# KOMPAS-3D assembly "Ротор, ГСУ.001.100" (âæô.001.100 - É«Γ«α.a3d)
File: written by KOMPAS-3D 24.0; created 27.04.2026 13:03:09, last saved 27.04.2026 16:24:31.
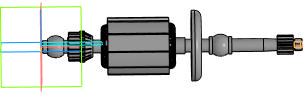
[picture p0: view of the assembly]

Document properties: Автор: User7; Полное имя файла: C:\Users\User7\Desktop\ГМ_27_04_337-02\ГСУ.001.100 - Ротор.a3d

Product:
- Component [detail]: Вал ротора  | designation ГСУ.001.102  | qty 1  | pos. 1  | Масса: 0.060205; Автор: User7; source file: ГСУ.001.102 - Вал ротора.m3d
- Component [detail]: Пропеллер  | designation ГСУ.001.104  | qty 1  | pos. 2  | Масса: 0.031447; Автор: User7; source file: ГСУ.001.104 - Пропеллер.m3d
- Component [detail]: Коллектор  | designation ГСУ.001.105  | qty 1  | pos. 3  | Масса: 0.0199; Автор: User7; source file: ГСУ.001.105 - Коллектор.m3d
- Component [detail]: Шайба  | designation ГСУ.001.106  | qty 2  | pos. 4  | Масса: 0.000703; Автор: User7; source file: ГСУ.001.106 - Шайба.m3d
- Component [detail]: Втулка  | designation ГСУ.001.107  | qty 2  | pos. 5  | Масса: 0.00612; Автор: User7; source file: ГСУ.001.107 - Втулка.m3d
- Component [detail]: Пластина  | designation ГСУ.001.108  | qty 10  | pos. 6  | Масса: 0.000055; Автор: User7; source file: ГСУ.001.108 - Пластина.m3d
- Component [detail]: Обмотка  | designation ГСУ.001.109  | qty 20  | pos. 7  | Масса: 0.002122; Автор: User7; source file: ГСУ.001.109 - Обмотка.m3d
- Component [detail]: Звездочка  | designation ГСУ.001.101  | qty 1  | pos. 8  | Масса: 0.070568; Автор: User7; source file: ГСУ.001.101 - Звездочка.m3d
- Component [standard]: Гайка М4-6H ГОСТ 15523-70  | qty 1  | Масса: 0.001183; Раздел спецификации: Стандартные изделия; Рассекать на разрезах: no
- Component [detail]: Шестеренка  | designation ГСУ.001.103  | qty 1  | pos. 9  | Масса: 0.003838; Автор: User7; source file: ГСУ.001.103 - Шестерня.m3d
- Component [detail]: Пластина  | designation ГСУ.001.110  | qty 10  | pos. 10  | Масса: 0.003574; Автор: User7; source file: ГСУ.001.110 - Пластина.m3d
- Part/product: Ротор  | designation ГСУ.001.100
    Масса: 0.279522

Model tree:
1. Средняя плоскость:1  (with: Грань.Элемент выдавливания:2)  (labels: Грань.Элемент выдавливания:2.Экземпляр ( 1, 2 ))
2. Массив по концентрической сетке:1  (with: Грань.Элемент вращения:1, Грань.Элемент выдавливания:1, Грань.Элемент выдавливания:2, Грань.Элемент по траектории:1, Средняя плоскость:1)  (labels: Грань.Элемент выдавливания:1.Экземпляр ( 110, 1 ); Грань.Элемент выдавливания:2.Экземпляр ( 1, 2 ))  (10 pattern instances)
     Шаг 2 = 360; Расстояние = -4; Расстояние = 2.5; Расстояние = 10; Расстояние = 19; Расстояние = 38.2; Расстояние = -162; Расстояние = 5.5; Расстояние = 19; Ориентация = 2; Угол = 162

Referenced files in C:\Users\User7\Desktop\ГМ_27_04_337-02\: ГСУ.001.102 - Вал ротора.m3d, ГСУ.001.104 - Пропеллер.m3d, ГСУ.001.105 - Коллектор.m3d, ГСУ.001.106 - Шайба.m3d, ГСУ.001.107 - Втулка.m3d, ГСУ.001.108 - Пластина.m3d, ГСУ.001.109 - Обмотка.m3d, ГСУ.001.101 - Звездочка.m3d, ГСУ.001.103 - Шестерня.m3d, ГСУ.001.110 - Пластина.m3d
Referenced files in C:\Program Files\ASCON\KOMPAS-3D v21\Libs\PARTLib\DATA\vault\Methods\Kompas\3D\: PLib_Nut_OST92_900.m3d
Referenced files in C:\Users\User7\Desktop\олимп\: ГСУ.001.106 - Шайба.m3d, ГСУ.001.107 - Втулка.m3d, ГСУ.001.108 - Пластина.m3d, ГСУ.001.110 - Пластина.m3d, ГСУ.001.109 - Обмотка.m3d
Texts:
  ГСУ.001.102
  ГСУ.001.104
  ГСУ.001.105
  ГСУ.001.106
  ГСУ.001.107
  ГСУ.001.108
  ГСУ.001.109
  ГСУ.001.101
  Крепежное изделие ГОСТ
  Программные изделия  и базы данных
  ГСУ.001.103
  ГСУ.001.110
  ГСУ.001.100
  Точка начала. Х
  Точка начала. Y
  Точка начала. Z
  ГСУ.001.102 Вал ротора
  ГСУ.001.104 Пропеллер
  ГСУ.001.105 Коллектор
  ГСУ.001.106 Шайба (1)
  ГСУ.001.107 Втулка (1)
  ГСУ.001.108 Пластина (1)
  ГСУ.001.109 Обмотка (1)
  ГСУ.001.101 Звездочка
  ГСУ.001.106 Шайба (2)
  ГСУ.001.107 Втулка (2)
  bcut1
  hole1
  hcut1
  hole2
  cut1
  ГСУ.001.103 Шестеренка
  ГСУ.001.110 Пластина (1)
  ГСУ.001.108 Пластина (2)
  ГСУ.001.110 Пластина (2)
  ГСУ.001.109 Обмотка (2)
  ГСУ.001.108 Пластина (3)
  ГСУ.001.110 Пластина (3)
  ГСУ.001.109 Обмотка (3)
  ГСУ.001.108 Пластина (4)
  ГСУ.001.110 Пластина (4)
  ГСУ.001.109 Обмотка (4)
  ГСУ.001.108 Пластина (5)
  ГСУ.001.110 Пластина (5)
  ГСУ.001.109 Обмотка (5)
  ГСУ.001.108 Пластина (6)
  ГСУ.001.110 Пластина (6)
  ГСУ.001.109 Обмотка (6)
  ГСУ.001.108 Пластина (7)
  ГСУ.001.110 Пластина (7)
  ГСУ.001.109 Обмотка (7)
  ГСУ.001.108 Пластина (8)
  ГСУ.001.110 Пластина (8)
  ГСУ.001.109 Обмотка (8)
  ГСУ.001.108 Пластина (9)
  ГСУ.001.110 Пластина (9)
  ГСУ.001.109 Обмотка (9)
  ГСУ.001.108 Пластина (10)
  ГСУ.001.110 Пластина (10)
  ГСУ.001.109 Обмотка (10)
  ГСУ.001.109 Обмотка (11)
  ГСУ.001.109 Обмотка (12)
  ГСУ.001.109 Обмотка (13)
  ГСУ.001.109 Обмотка (14)
  ГСУ.001.109 Обмотка (15)
  ГСУ.001.109 Обмотка (16)
  ГСУ.001.109 Обмотка (17)
  ГСУ.001.109 Обмотка (18)
  ГСУ.001.109 Обмотка (19)
  ГСУ.001.109 Обмотка (20)
  Ось X.Начало координат
  Плоскость ZX.Начало координат
  Плоскость XY.Начало координат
